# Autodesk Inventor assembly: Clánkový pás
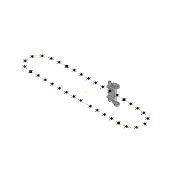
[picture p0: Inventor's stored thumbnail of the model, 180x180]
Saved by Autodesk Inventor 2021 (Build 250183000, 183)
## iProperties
Created: 2024-12
Part Number: Clánkový pás
Document SubType Name: Assembly
Designer: tatulinek
Author: tatulinek
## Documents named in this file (3)
- C:\Users\tatulinek\Documents\____Zviratka\Pas\Clánkový pás.iam
- C:\Users\tatulinek\Documents\____Zviratka\Pas\Clanek.ipt
- C:\Users\tatulinek\Documents\____Zviratka\Pas\Pas_geometrie1.ipt
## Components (2 placed, 2 different names)
1. Clanek:1 — Stejný směr:1
2. Pas_geometrie1:1 — Stejný směr:1
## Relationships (1: Flush 1)
- Stejný směr:1 [Flush]: Clanek:1 ↔ Pas_geometrie1:1
